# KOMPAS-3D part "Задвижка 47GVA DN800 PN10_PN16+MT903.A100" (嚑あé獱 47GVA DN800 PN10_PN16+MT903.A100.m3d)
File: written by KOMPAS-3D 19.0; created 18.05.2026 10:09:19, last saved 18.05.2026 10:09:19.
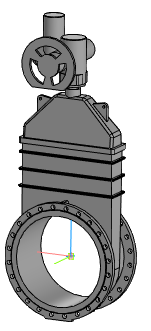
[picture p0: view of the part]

Document properties: Автор: Энергия; Полное имя файла: ..\Задвижка 47GVA DN40_DN1000+MT903.A\Задвижка 47GVA DN800 PN10_PN16+MT903.A100.a3d

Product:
- Part/product: Задвижка 47GVA DN800 PN10_PN16+MT903.A100
    Масса: 1994.42
  - Body: Электропривод МТ903.А100 без блока управления
      Масса: 346.451
  - Body: Задвижка 47GVA DN800 PN10_PN16_F16 без исполнительного механизма
      Масса: 1647.97

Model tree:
1. Операция без истории:1
2. Операция без истории:2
